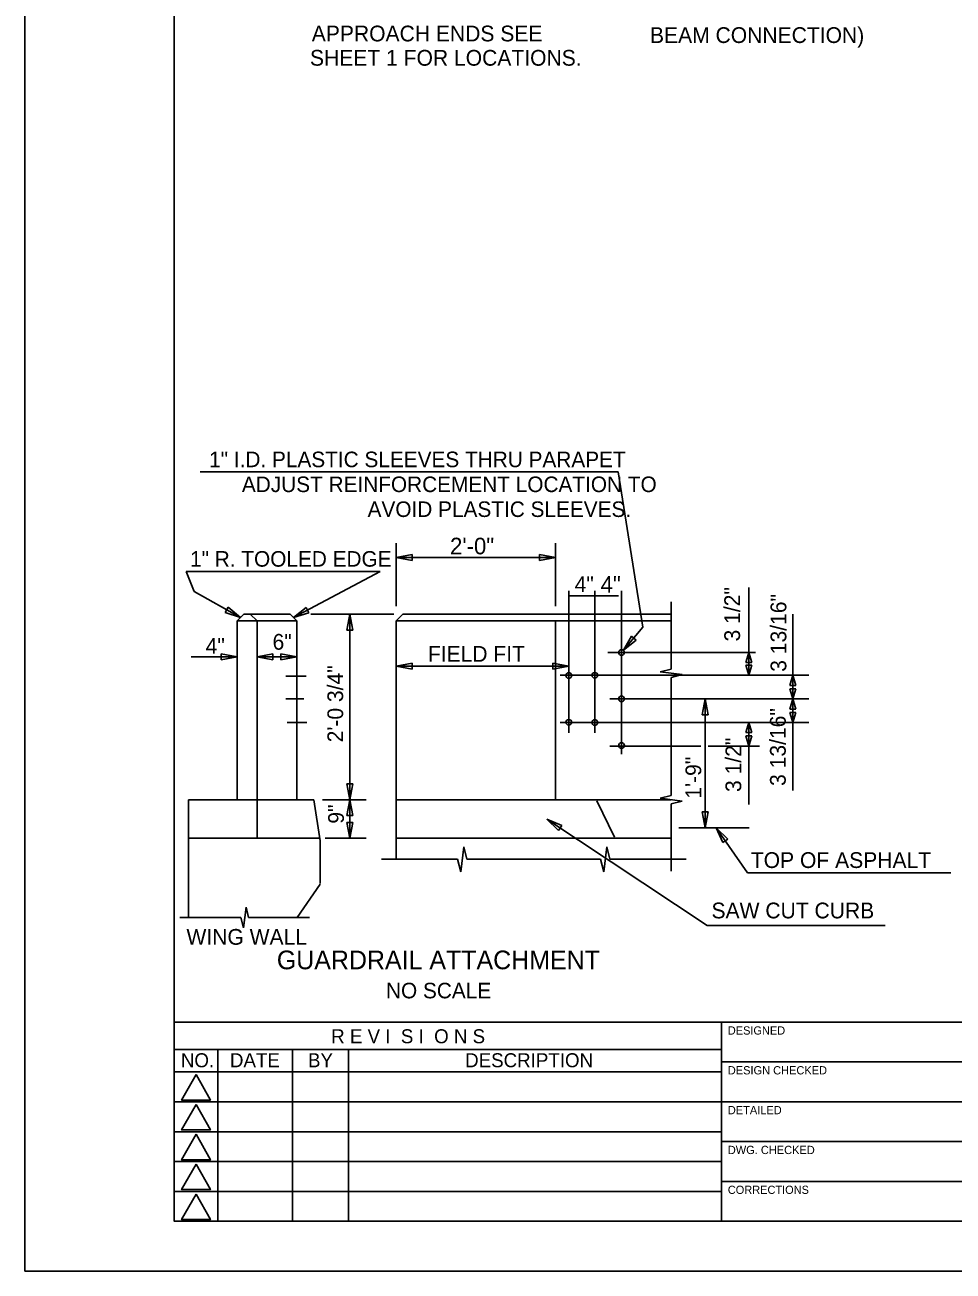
# Model space of a CAD drawing. Extents: x 0 to 34.5, y 0 to 23.5.
# Drawn here: x 0 to 9.33, y 0 to 12.51 of the extents above; entities that cross this region are included whole.
import ezdxf

# ---------------------------------------------------------------- set-up
doc = ezdxf.new("R2010")
doc.units = 0
for name, color, linetype in [('BORDER_ANNO_Cutsheet', 7, 'Continuous'), ('BRDG_ANNO_Anno-Sheet', 7, 'Continuous'), ('BRDG_ANNO_General-Notes', 7, 'Continuous'), ('BRDG_BASE_Active-Point', 7, 'Continuous'), ('BRDG_BASE_Dtlctrln', 7, 'Continuous'), ('BRDG_BASE_Obj-Line', 7, 'Continuous')]:
    doc.layers.add(name, color=color, linetype=linetype)

msp = doc.modelspace()

# ---------------------------------------------------------------- linework, layer by layer
at = {"layer": 'BORDER_ANNO_Cutsheet'}
msp.add_lwpolyline([(0, 22), (34, 22), (34, 0), (0, 0)], close=True, dxfattribs=at)
at = {"layer": 'BRDG_ANNO_Anno-Sheet'}
for p, q in [((1.5, 2.5), (19.25, 2.5)), ((7, 0.5), (7, 2.5)), ((1.5, 2.225), (7, 2.225)), ((1.938, 0.5), (1.938, 2.225)), ((2.688, 0.5), (2.688, 2.225)), ((3.25, 0.5), (3.25, 2.219)), ((7, 2.1), (9.5, 2.1)), ((1.498, 2), (7, 2)), ((1.498, 1.7), (7, 1.7)), ((7, 1.7), (9.5, 1.7)), ((1.498, 1.4), (7, 1.4)), ((7, 1.3), (9.5, 1.3)), ((1.498, 1.1), (7, 1.1)), ((7, 0.9), (9.5, 0.9)), ((1.498, 0.8), (7, 0.8))]:
    msp.add_line(p, q, dxfattribs=at)
msp.add_lwpolyline([(1.5, 21.5), (33.5, 21.5), (33.5, 0.5), (1.5, 0.5)], close=True, dxfattribs=at)
for points in [[(1.722, 1.974), (1.574, 1.718), (1.864, 1.718), (1.722, 1.974)], [(1.722, 1.674), (1.574, 1.417), (1.864, 1.417), (1.722, 1.674)], [(1.722, 1.374), (1.574, 1.117), (1.864, 1.117), (1.722, 1.374)], [(1.722, 1.074), (1.574, 0.818), (1.864, 0.818), (1.722, 1.074)], [(1.722, 0.774), (1.574, 0.517), (1.864, 0.517), (1.722, 0.774)]]:
    msp.add_lwpolyline(points, dxfattribs=at)
at = {"layer": 'BRDG_ANNO_General-Notes'}
for p, q in [((1.76, 8.028), (5.961, 8.028)), ((5.961, 8.028), (6.209, 6.465)), ((3.73, 6.679), (3.73, 7.311)), ((5.33, 6.679), (5.33, 7.311)), ((3.73, 7.166), (3.89, 7.196)), ((3.73, 7.166), (5.33, 7.166)), ((3.89, 7.136), (3.73, 7.166)), ((3.89, 7.196), (3.89, 7.136)), ((5.17, 7.136), (5.17, 7.196)), ((5.17, 7.196), (5.33, 7.166)), ((5.33, 7.166), (5.17, 7.136)), ((1.621, 7.026), (3.568, 7.026)), ((1.621, 7.026), (1.699, 6.823)), ((2.698, 6.563), (3.568, 7.026)), ((2.166, 6.563), (1.699, 6.823)), ((5.725, 6.781), (5.464, 6.781)), ((5.964, 6.781), (5.725, 6.781)), ((7.274, 6.866), (7.274, 6.213)), ((2.012, 6.615), (2.041, 6.667)), ((2.041, 6.667), (2.166, 6.563)), ((2.698, 6.563), (2.825, 6.665)), ((2.825, 6.665), (2.854, 6.612)), ((2.166, 6.563), (2.012, 6.615)), ((2.854, 6.612), (2.698, 6.563)), ((3.707, 6.596), (2.872, 6.596)), ((3.234, 6.438), (3.264, 6.598)), ((3.264, 4.734), (3.264, 6.598)), ((3.264, 6.598), (3.294, 6.438)), ((7.715, 5.983), (7.715, 6.596)), ((3.294, 6.438), (3.234, 6.438)), ((6.209, 6.465), (6.014, 6.234)), ((6.014, 6.234), (6.094, 6.376)), ((6.14, 6.337), (6.014, 6.234)), ((6.094, 6.376), (6.14, 6.337)), ((1.669, 6.168), (2.132, 6.168)), ((1.972, 6.138), (1.972, 6.198)), ((1.972, 6.198), (2.132, 6.168)), ((2.132, 6.168), (1.972, 6.138)), ((2.332, 6.168), (2.492, 6.198)), ((2.332, 6.168), (2.732, 6.168)), ((2.492, 6.138), (2.332, 6.168)), ((2.492, 6.198), (2.492, 6.138)), ((2.572, 6.138), (2.572, 6.198)), ((2.572, 6.198), (2.732, 6.168)), ((2.732, 6.168), (2.572, 6.138)), ((7.244, 6.111), (7.274, 6.213)), ((7.274, 6.213), (7.274, 5.983)), ((7.274, 6.213), (7.304, 6.111)), ((3.73, 6.076), (3.89, 6.106)), ((3.73, 6.076), (5.464, 6.076)), ((3.89, 6.046), (3.73, 6.076)), ((3.89, 6.106), (3.89, 6.046)), ((5.304, 6.046), (5.304, 6.106)), ((5.304, 6.106), (5.464, 6.076)), ((5.464, 6.076), (5.304, 6.046)), ((7.304, 6.111), (7.244, 6.111)), ((7.244, 6.085), (7.304, 6.085)), ((7.274, 5.983), (7.244, 6.085)), ((7.304, 6.085), (7.274, 5.983)), ((7.685, 5.881), (7.715, 5.983)), ((7.715, 5.746), (7.715, 5.983)), ((7.715, 5.983), (7.745, 5.881)), ((7.745, 5.881), (7.685, 5.881)), ((7.685, 5.848), (7.745, 5.848)), ((7.715, 5.746), (7.685, 5.848)), ((7.745, 5.848), (7.715, 5.746)), ((6.803, 5.586), (6.833, 5.746)), ((6.833, 4.452), (6.833, 5.746)), ((6.833, 5.746), (6.863, 5.586)), ((7.685, 5.644), (7.715, 5.746)), ((7.745, 5.644), (7.685, 5.644)), ((7.715, 5.746), (7.715, 5.509)), ((7.715, 5.746), (7.745, 5.644)), ((6.863, 5.586), (6.803, 5.586)), ((7.244, 5.407), (7.274, 5.509)), ((7.274, 5.272), (7.274, 5.509)), ((7.274, 5.509), (7.304, 5.407)), ((7.685, 5.611), (7.745, 5.611)), ((7.715, 5.509), (7.685, 5.611)), ((7.745, 5.611), (7.715, 5.509)), ((7.715, 5.509), (7.715, 4.827)), ((7.304, 5.407), (7.244, 5.407)), ((7.244, 5.374), (7.304, 5.374)), ((7.274, 5.272), (7.244, 5.374)), ((7.304, 5.374), (7.274, 5.272)), ((7.274, 4.685), (7.274, 5.272)), ((3.234, 4.894), (3.294, 4.894)), ((3.264, 4.734), (3.234, 4.894)), ((3.294, 4.894), (3.264, 4.734)), ((3.43, 4.734), (2.99, 4.734)), ((3.234, 4.574), (3.264, 4.734)), ((3.264, 4.346), (3.264, 4.734)), ((3.264, 4.734), (3.294, 4.574)), ((3.294, 4.574), (3.234, 4.574)), ((3.234, 4.506), (3.294, 4.506)), ((3.264, 4.346), (3.234, 4.506)), ((3.294, 4.506), (3.264, 4.346)), ((5.243, 4.538), (6.855, 3.471)), ((5.36, 4.425), (5.243, 4.538)), ((5.243, 4.538), (5.393, 4.475)), ((6.803, 4.612), (6.863, 4.612)), ((6.833, 4.452), (6.803, 4.612)), ((6.863, 4.612), (6.833, 4.452)), ((5.393, 4.475), (5.36, 4.425)), ((6.57, 4.452), (7.275, 4.452)), ((6.946, 4.452), (7.259, 4.001)), ((7.013, 4.303), (6.946, 4.452)), ((6.946, 4.452), (7.062, 4.337)), ((3.43, 4.346), (3.015, 4.346)), ((7.062, 4.337), (7.013, 4.303)), ((7.259, 4.001), (9.302, 4.001)), ((6.855, 3.471), (8.644, 3.471))]:
    msp.add_line(p, q, dxfattribs=at)
at = {"layer": 'BRDG_BASE_Active-Point'}
msp.add_line((0, 0), (0, 0), dxfattribs=at)
at = {"layer": 'BRDG_BASE_Dtlctrln'}
for p, q in [((5.464, 5.406), (5.464, 6.83)), ((5.725, 5.406), (5.725, 6.83)), ((5.993, 5.191), (5.993, 6.83)), ((5.856, 6.213), (7.341, 6.213)), ((2.623, 5.976), (2.826, 5.976)), ((5.376, 5.983), (7.877, 5.983)), ((2.623, 5.746), (2.803, 5.746)), ((5.876, 5.746), (7.877, 5.746)), ((2.634, 5.509), (2.834, 5.509)), ((5.376, 5.509), (7.877, 5.509)), ((5.876, 5.272), (6.79, 5.272)), ((6.864, 5.272), (7.38, 5.272))]:
    msp.add_line(p, q, dxfattribs=at)
at = {"layer": 'BRDG_BASE_Obj-Line'}
for p, q in [((6.494, 6.721), (6.494, 6.045)), ((2.2, 6.597), (2.132, 6.529)), ((2.132, 4.734), (2.132, 6.529)), ((2.132, 6.529), (2.732, 6.529)), ((2.2, 6.597), (2.664, 6.597)), ((2.264, 6.597), (2.332, 6.529)), ((2.332, 4.347), (2.332, 6.529)), ((2.664, 6.597), (2.732, 6.529)), ((2.732, 4.734), (2.732, 6.529)), ((3.797, 6.596), (3.73, 6.529)), ((3.73, 4.135), (3.73, 6.529)), ((3.73, 6.529), (6.494, 6.529)), ((3.797, 6.596), (6.494, 6.596)), ((5.33, 4.734), (5.33, 6.529)), ((6.384, 6.018), (6.494, 6.045)), ((6.604, 5.99), (6.384, 6.018)), ((6.494, 5.962), (6.604, 5.99)), ((6.494, 5.962), (6.494, 4.775)), ((6.384, 4.748), (6.494, 4.775)), ((1.645, 4.734), (2.904, 4.734)), ((1.645, 3.551), (1.645, 4.734)), ((2.965, 4.321), (2.904, 4.734)), ((3.73, 4.734), (6.494, 4.734)), ((5.923, 4.356), (5.747, 4.721)), ((6.604, 4.72), (6.384, 4.748)), ((6.494, 4.692), (6.604, 4.72)), ((6.494, 4.692), (6.494, 4.016)), ((1.645, 4.347), (2.962, 4.347)), ((2.965, 3.891), (2.965, 4.321)), ((3.73, 4.346), (6.494, 4.346)), ((4.378, 4.01), (4.409, 4.26)), ((4.409, 4.26), (4.441, 4.135)), ((5.816, 4.01), (5.847, 4.26)), ((5.847, 4.26), (5.878, 4.135)), ((4.347, 4.135), (3.581, 4.135)), ((4.347, 4.135), (4.378, 4.01)), ((5.784, 4.135), (4.441, 4.135)), ((5.784, 4.135), (5.816, 4.01)), ((6.644, 4.135), (5.878, 4.135)), ((2.734, 3.551), (2.965, 3.885)), ((2.196, 3.447), (2.222, 3.655)), ((2.222, 3.655), (2.248, 3.551)), ((2.17, 3.551), (1.558, 3.551)), ((2.17, 3.551), (2.196, 3.447)), ((2.86, 3.551), (2.248, 3.551))]:
    msp.add_line(p, q, dxfattribs=at)
for centre in [(5.994, 6.213), (5.464, 5.981), (5.725, 5.983), (5.994, 5.746), (5.464, 5.511), (5.725, 5.509), (5.994, 5.278)]:
    msp.add_circle(centre, 0.0284, dxfattribs=at)

# ---------------------------------------------------------------- texts
at = {"layer": 'BRDG_ANNO_Anno-Sheet'}
for s, height, p in [('R E V I  S I  O N S', 0.14062, (3.077, 2.288)), ('DESIGNED', 0.0825, (7.062, 2.375)), ('NO.', 0.1406, (1.567, 2.047)), ('DATE', 0.1406, (2.06, 2.047)), ('BY', 0.1406, (2.844, 2.047)), ('DESCRIPTION', 0.14062, (4.423, 2.047)), ('DESIGN CHECKED', 0.08281, (7.062, 1.975)), ('DETAILED', 0.0828, (7.062, 1.575)), ('DWG. CHECKED', 0.08281, (7.062, 1.175)), ('CORRECTIONS', 0.0825, (7.062, 0.775))]:
    msp.add_text(s, height=height, dxfattribs=at).set_placement(p)
at = {"layer": 'BRDG_ANNO_General-Notes'}
for s, height, p in [('APPROACH ENDS SEE ', 0.15833, (2.882, 12.349)), ('BEAM CONNECTION)', 0.15833, (6.28, 12.333)), ('SHEET 1 FOR LOCATIONS.', 0.15833, (2.864, 12.105)), ('1" I.D. PLASTIC SLEEVES THRU PARAPET', 0.15625, (1.851, 8.073)), ('ADJUST REINFORCEMENT LOCATION TO', 0.15625, (2.18, 7.823)), ('AVOID PLASTIC SLEEVES.', 0.15625, (3.443, 7.573)), ('2\'-0"', 0.1667, (4.271, 7.198)), ('1" R. TOOLED EDGE', 0.15625, (1.659, 7.074)), ('4"', 0.1583, (5.523, 6.819)), ('4"', 0.1667, (5.784, 6.812)), ('6"', 0.1583, (2.488, 6.24)), ('4"', 0.1583, (1.816, 6.199)), ('FIELD FIT', 0.1583, (4.048, 6.119)), ('TOP OF ASPHALT', 0.15833, (7.293, 4.048)), ('SAW CUT CURB', 0.15833, (6.898, 3.542)), ('WING WALL', 0.1583, (1.623, 3.277)), ('GUARDRAIL ATTACHMENT', 0.1875, (2.531, 3.031)), ('NO SCALE', 0.1562, (3.628, 2.739))]:
    msp.add_text(s, height=height, dxfattribs=at).set_placement(p)
for s, height, p in [('3 1/2"', 0.1583, (7.185, 6.323)), ('3 13/16"', 0.1583, (7.65, 6.018)), ('2\'-0 3/4"', 0.158, (3.197, 5.31)), ('3 13/16"', 0.1583, (7.644, 4.872)), ('3 1/2"', 0.1583, (7.197, 4.811)), ('1\'-9"', 0.1583, (6.795, 4.744)), ('9"', 0.1583, (3.205, 4.493))]:
    msp.add_text(s, height=height, rotation=90, dxfattribs=at).set_placement(p)

doc.saveas('drawing.dxf')
